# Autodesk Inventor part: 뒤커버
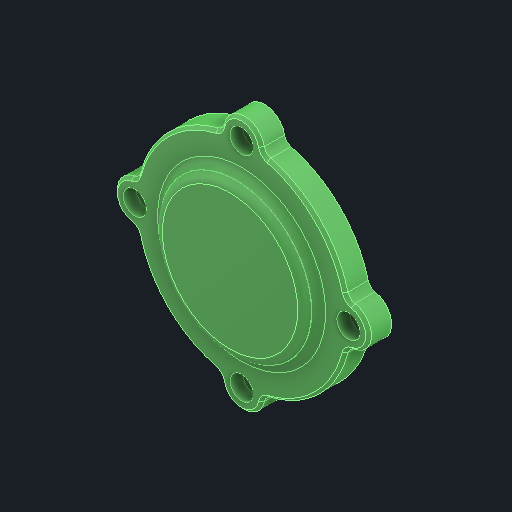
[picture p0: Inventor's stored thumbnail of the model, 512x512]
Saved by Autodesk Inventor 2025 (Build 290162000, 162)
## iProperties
Created: 2025-08
Part Number: 뒤커버
Material: 알루미늄 6061
Document SubType Name: Modeling
Designer: infra005
Density: 2.71 g/cm^3
Appearance: 기본값
Company: 한국ATC센터
Author: jhkim
Sending System: Autodesk Inventor 2026
Preprocessor: ST-DEVELOPER v20.1
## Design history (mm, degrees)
feature "솔리드1"
node "솔리드2"
